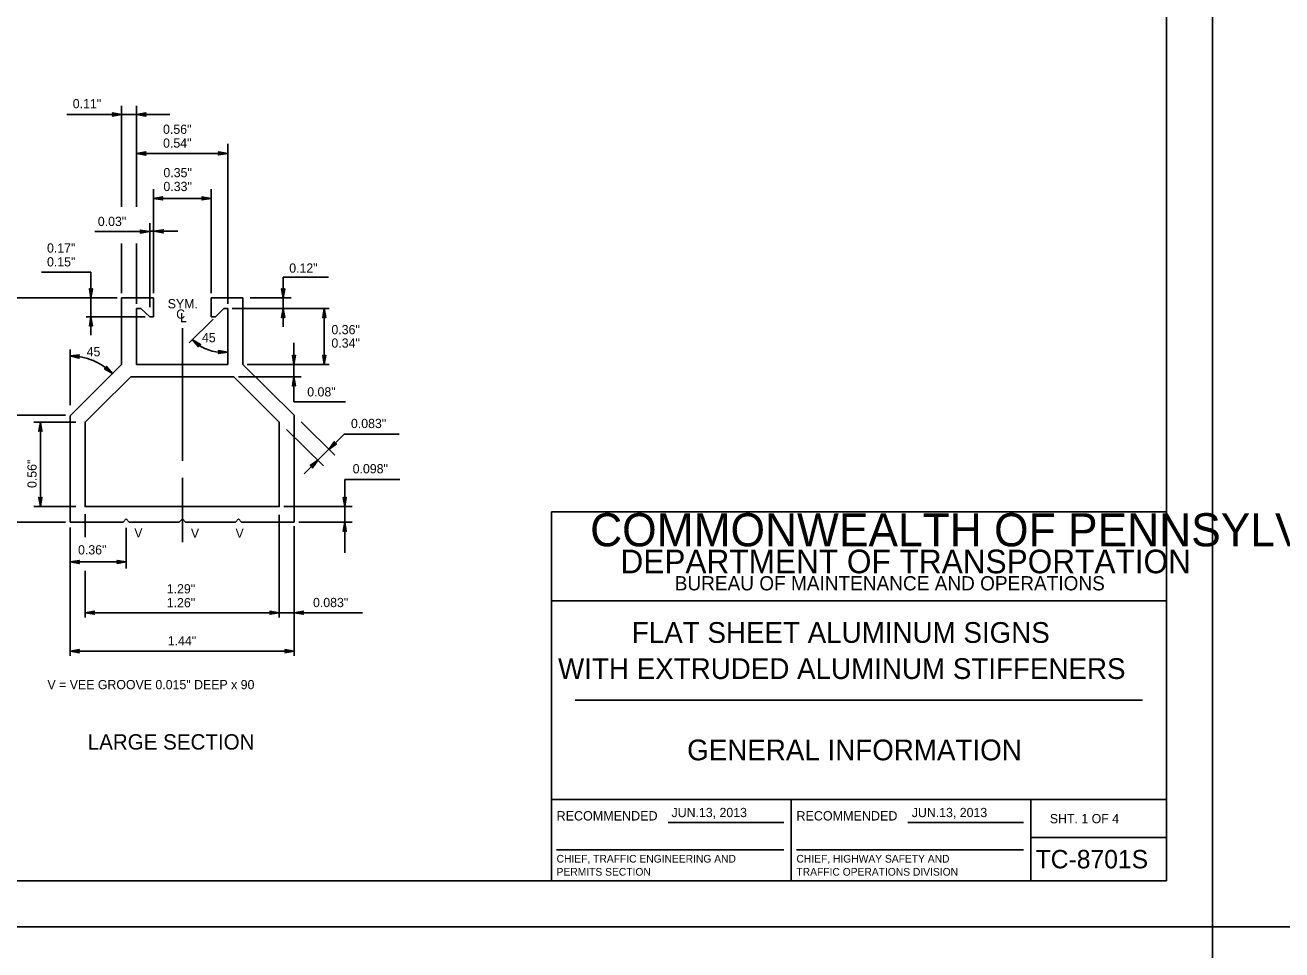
# Model space of a CAD drawing. Extents: x 650495 to 652241, y 298458 to 299646.
# Drawn here: x 650950.2 to 651358.9, y 299044.1 to 299344.9 of the extents above; entities that cross this region are included whole.
import ezdxf

# ---------------------------------------------------------------- set-up
doc = ezdxf.new("R2010")
doc.units = 0
for name, color, linetype in [('1', 7, 'Continuous'), ('2', 7, 'Continuous'), ('3', 7, 'Continuous'), ('PLT-BNDY', 7, 'Continuous')]:
    doc.layers.add(name, color=color, linetype=linetype)

# ---------------------------------------------------------------- blocks, each defined once
blk = doc.blocks.new('RARROW')
at = {"layer": '3'}
blk.add_lwpolyline([(-2.2695, 0.285), (-2.184875, 0.12075), (0, 0), (-2.2695, 0.285), (-2.38575, 0.384625), (0, 0), (-2.183125, -0.108), (-2.262875, -0.2705), (0, 0), (-2.38575, -0.379125), (-2.262875, -0.2705)], dxfattribs=at)

msp = doc.modelspace()

# ---------------------------------------------------------------- linework, layer by layer
at = {"layer": '1'}
for p, q in [((651321.31, 299066.63), (651321.31, 299630.63)), ((651121.31, 299066.63), (651121.31, 299186.63)), ((651121.31, 299186.63), (651321.31, 299186.63)), ((651321.31, 299157.63), (651121.31, 299157.63)), ((651129.06, 299125.31), (651313.56, 299125.31)), ((651121.31, 299093), (651321.31, 299093)), ((651199.31, 299093), (651199.31, 299066.63)), ((651277.19, 299066.63), (651277.19, 299093)), ((651159.24, 299085.57), (651196.87, 299085.57)), ((651237.24, 299085.57), (651274.87, 299085.57)), ((651277.19, 299080.63), (651321.31, 299080.63)), ((651122.99, 299076.68), (651196.87, 299076.68)), ((651200.99, 299076.68), (651274.87, 299076.68)), ((651321.31, 299066.63), (650535.31, 299066.63)), ((650535.31, 299066.63), (651121.31, 299066.63))]:
    msp.add_line(p, q, dxfattribs=at)
at = {"layer": '2'}
for p, q in [((650981.53, 299285.77), (650981.53, 299318.65)), ((650986.41, 299285.77), (650986.41, 299318.65)), ((650963.75, 299315.82), (650981.53, 299315.82)), ((650981.53, 299315.82), (650997.19, 299315.82)), ((651016.03, 299254.27), (651016.03, 299306.22)), ((650986.41, 299303.14), (651016.03, 299303.14)), ((650991.91, 299257.65), (650991.91, 299291.57)), ((651010.66, 299257.65), (651010.66, 299291.57)), ((650991.91, 299288.52), (651010.66, 299288.52)), ((650972.87, 299277.73), (650990.57, 299277.73)), ((650990.66, 299253.19), (650990.66, 299280.52)), ((650990.66, 299277.82), (650999.82, 299277.82)), ((650981.53, 299257.65), (650981.53, 299273.89)), ((650986.41, 299254.27), (650986.41, 299273.89)), ((650955.46, 299264.51), (650971.55, 299264.51)), ((650971.55, 299264.51), (650971.55, 299256.15)), ((651034.07, 299262.9), (651034.07, 299256.15)), ((651034.07, 299262.9), (651048.84, 299262.9)), ((650980.03, 299256.15), (650930.42, 299256.15)), ((650971.55, 299244.02), (650971.55, 299256.15)), ((650981.53, 299234.52), (650981.53, 299256.15)), ((650981.53, 299256.15), (650991.91, 299256.15)), ((650991.91, 299250.02), (650991.91, 299256.15)), ((651010.66, 299256.15), (651020.91, 299256.15)), ((651010.66, 299250.02), (651010.66, 299256.15)), ((651020.91, 299256.15), (651020.91, 299234.52)), ((651023.39, 299256.15), (651036.63, 299256.15)), ((651034.07, 299246.77), (651034.07, 299256.15)), ((650989.16, 299250.02), (650970.05, 299250.02)), ((650986.41, 299252.77), (650986.41, 299234.52)), ((650987.78, 299252.77), (650986.41, 299252.77)), ((650987.78, 299252.77), (650990.66, 299250.02)), ((650990.66, 299250.02), (650991.91, 299250.02)), ((651011.26, 299249.24), (651003.54, 299241.5)), ((651010.66, 299250.02), (651012.04, 299250.02)), ((651014.78, 299252.77), (651012.04, 299250.02)), ((651014.78, 299252.77), (651016.03, 299252.77)), ((651016.03, 299252.77), (651016.03, 299234.52)), ((651017.53, 299252.77), (651048.98, 299252.77)), ((651047.42, 299252.77), (651047.42, 299234.52)), ((651001.28, 299203.15), (651001.28, 299246.34)), ((651037.58, 299241.55), (651037.58, 299234.52)), ((650964.78, 299221.31), (650964.78, 299239.4)), ((651013.4, 299238.53), (651016.03, 299238.53)), ((650964.78, 299217.77), (650981.53, 299234.52)), ((650986.41, 299234.52), (650999.16, 299234.52)), ((651001.28, 299234.52), (651007.78, 299234.52)), ((651007.78, 299234.52), (651016.03, 299234.52)), ((651020.91, 299234.52), (651037.66, 299218.02)), ((651022.41, 299234.52), (651048.98, 299234.52)), ((651037.58, 299234.52), (651037.58, 299222.4)), ((651019.53, 299230.52), (651039.96, 299230.52)), ((651037.58, 299222.4), (651054.37, 299222.4)), ((650963.28, 299218.03), (650937.68, 299218.03)), ((650964.78, 299183.27), (650964.78, 299217.77)), ((651037.66, 299218.02), (651037.66, 299183.27)), ((650952.95, 299215.77), (650966.6, 299215.77)), ((650955.1, 299215.77), (650955.1, 299188.27)), ((651035.2, 299213.38), (651047.2, 299201.57)), ((651039.89, 299215.81), (651050.84, 299205.03)), ((651045.37, 299203.36), (651053.91, 299211.9)), ((651053.91, 299211.9), (651071.77, 299211.9)), ((651040.91, 299198.9), (651045.37, 299203.36)), ((651001.28, 299176.77), (651001.28, 299197.65)), ((651054.09, 299197.15), (651072.05, 299197.15)), ((651054.09, 299197.15), (651054.09, 299188.27)), ((650952.95, 299188.27), (650966.6, 299188.27)), ((651034.28, 299188.27), (651056.47, 299188.27)), ((651054.09, 299188.27), (651054.09, 299173.21)), ((650969.66, 299185.85), (650969.66, 299178.3)), ((650983.03, 299184.27), (650982.03, 299183.27)), ((650984.03, 299183.27), (650983.03, 299184.27)), ((651000.28, 299183.27), (651001.28, 299184.27)), ((651001.28, 299184.27), (651000.28, 299183.27)), ((651002.28, 299183.27), (651001.28, 299184.27)), ((651018.53, 299183.27), (651019.53, 299184.27)), ((651019.53, 299184.27), (651018.53, 299183.27)), ((651019.53, 299184.27), (651020.53, 299183.27)), ((651020.53, 299183.27), (651019.53, 299184.27)), ((651032.78, 299185.62), (651032.78, 299152.27)), ((650963.28, 299183.27), (650930.42, 299183.27)), ((650982.03, 299183.27), (650964.78, 299183.27)), ((650964.78, 299181.46), (650964.78, 299139.77)), ((650983.03, 299181.37), (650983.03, 299168.17)), ((651000.28, 299183.27), (650984.03, 299183.27)), ((651018.53, 299183.27), (651002.28, 299183.27)), ((651037.66, 299183.27), (651020.53, 299183.27)), ((651037.66, 299181.93), (651037.66, 299139.77)), ((651039.16, 299183.27), (651056.47, 299183.27)), ((650964.78, 299170.3), (650983.03, 299170.3)), ((650969.66, 299167.44), (650969.66, 299152.27)), ((650969.66, 299153.77), (651032.78, 299153.77)), ((651059.89, 299153.77), (651032.78, 299153.77)), ((650964.78, 299141.27), (651037.66, 299141.27))]:
    msp.add_line(p, q, dxfattribs=at)
for points in [[(650999.16, 299234.52), (651001.28, 299234.52)], [(650984.53, 299230.52), (650973.78, 299219.9)], [(650999.16, 299230.52), (650984.53, 299230.52)], [(651001.28, 299230.52), (650999.16, 299230.52)], [(651007.78, 299230.52), (651001.28, 299230.52)], [(651018.03, 299230.52), (651007.78, 299230.52)], [(651023.78, 299224.77), (651018.03, 299230.52)], [(651032.78, 299200.15), (651032.78, 299215.77), (651023.78, 299224.77)], [(650973.78, 299219.9), (650969.66, 299215.77), (650969.66, 299188.27), (650973.78, 299188.27)], [(651007.78, 299188.27), (651032.78, 299188.27), (651032.78, 299200.15)], [(650973.78, 299188.27), (651001.28, 299188.27)], [(651001.28, 299188.27), (651005.91, 299188.27)], [(651005.91, 299188.27), (651007.78, 299188.27)]]:
    msp.add_lwpolyline(points, dxfattribs=at)
for centre, radius, start, end in [((651014, 299251.58), 13.06, 223.8098, 267.3752), ((650964.78, 299217.77), 19.5, 45, 90)]:
    msp.add_arc(centre, radius, start, end, dxfattribs=at)
at = {"layer": 'PLT-BNDY'}
for points in [[(650495.31, 299645.63), (651336.31, 299645.63), (651336.31, 299051.63), (650495.31, 299051.63)], [(651336.31, 299645.63), (652177.31, 299645.63), (652177.31, 299051.63), (651336.31, 299051.63)], [(650495.31, 299051.63), (651336.31, 299051.63), (651336.31, 298457.63), (650495.31, 298457.63)], [(651336.31, 299051.63), (652177.31, 299051.63), (652177.31, 298457.63), (651336.31, 298457.63)]]:
    msp.add_lwpolyline(points, close=True, dxfattribs=at)

# ---------------------------------------------------------------- block references
at = {"layer": '2', "xscale": 1.2574347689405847, "yscale": 1.3092961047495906}
for p in [(650981.53, 299315.82), (651016.03, 299303.14), (651010.66, 299288.52), (650990.57, 299277.73), (651016.03, 299238.53), (650983.03, 299170.3), (651032.78, 299153.77), (651037.66, 299141.27)]:
    msp.add_blockref('RARROW', p, dxfattribs=at)
at = {"layer": '2'}
for p, xscale, yscale, rotation in [((650986.41, 299315.82), 1.2574347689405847, 1.3092961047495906, 180), ((650986.41, 299303.14), 1.2574347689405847, 1.3092961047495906, 180), ((650991.91, 299288.52), 1.2574347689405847, 1.3092961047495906, 180), ((650992.09, 299277.82), 1.2574347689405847, 1.3092961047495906, 180), ((650971.55, 299256.15), 1.2574347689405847, 1.3092961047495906, -90.00000000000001), ((651034.07, 299256.15), 1.2574347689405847, 1.3092961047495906, -90.00000000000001), ((650971.55, 299250.02), 1.2574347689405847, 1.3092961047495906, 89.99999999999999), ((651034.07, 299252.77), 1.2574347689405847, 1.3092961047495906, 89.99999999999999), ((651047.42, 299252.77), 1.2574347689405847, 1.3092961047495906, 89.99999999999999), ((651004.57, 299242.54), 1.2574347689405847, 1.3092961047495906, 140.9194989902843), ((650964.78, 299237.27), 1.2574347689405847, 1.3092961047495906, 176.80414646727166), ((651037.58, 299234.52), 1.2574347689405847, 1.3092961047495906, -90.00000000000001), ((651047.42, 299234.52), 1.2574347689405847, 1.3092961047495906, -90.00000000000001), ((650978.57, 299231.56), 1.2574347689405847, 1.3092961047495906, -40.89957129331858), ((651037.58, 299230.52), 1.2574347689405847, 1.3092961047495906, 89.99999999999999), ((650955.1, 299215.77), 1.2574347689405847, 1.3092961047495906, 89.99999999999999), ((651048.93, 299206.89), 1.2574347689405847, 1.3092961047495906, -134.02087905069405), ((651045.37, 299203.36), 1.2574347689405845, 1.3092961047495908, 44.7961575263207), ((650955.1, 299188.27), 1.2574347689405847, 1.3092961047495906, -90.00000000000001), ((651054.09, 299188.27), 1.2574347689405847, 1.3092961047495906, -90.00000000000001), ((651054.09, 299183.27), 1.2574347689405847, 1.3092961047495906, 89.99999999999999), ((650964.78, 299170.3), 1.2574347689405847, 1.3092961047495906, 180), ((650969.66, 299153.77), 1.2574347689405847, 1.3092961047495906, 180), ((651037.66, 299153.77), 1.2574347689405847, 1.3092961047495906, 180), ((650964.78, 299141.27), 1.2574347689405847, 1.3092961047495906, 180)]:
    msp.add_blockref('RARROW', p, dxfattribs=dict(at, xscale=xscale, yscale=yscale, rotation=rotation))

# ---------------------------------------------------------------- texts
at = {"layer": '1'}
for s, height, p in [('COMMONWEALTH OF PENNSYLVANIA', 10.7828, (651133.9, 299175.36)), ('DEPARTMENT OF TRANSPORTATION', 7.6837, (651143.76, 299166.61)), ('BUREAU OF MAINTENANCE AND OPERATIONS', 4.6253, (651161.41, 299161.04)), ('FLAT SHEET ALUMINUM SIGNS', 6.75, (651147.47, 299143.97)), ('WITH EXTRUDED ALUMINUM STIFFENERS', 6.75, (651123.47, 299132.22)), ('GENERAL INFORMATION', 6.75, (651165.45, 299105.78)), ('RECOMMENDED', 3.048, (651122.99, 299086.2)), ('RECOMMENDED', 3.048, (651200.99, 299086.2)), ('SHT. 1 OF 4', 3, (651283.4, 299085.31)), ('CHIEF, TRAFFIC ENGINEERING AND', 2.5, (651122.99, 299072.51)), ('CHIEF, HIGHWAY SAFETY AND', 2.5, (651200.99, 299072.51)), ('TC-8701S', 6, (651278.79, 299070.63)), ('PERMITS SECTION', 2.5, (651122.99, 299068.26)), ('TRAFFIC OPERATIONS DIVISION', 2.5, (651200.99, 299068.26))]:
    msp.add_text(s, height=height, dxfattribs=at).set_placement(p)
at = {"layer": '2'}
for s, height, p in [('0.11"', 3, (650965.65, 299317.84)), ('0.56"', 3, (650995.01, 299309.52)), ('0.54"', 3, (650995.01, 299305.02)), ('0.35"', 3, (650995.13, 299295.41)), ('0.33"', 3, (650995.13, 299290.91)), ('0.03"', 3, (650973.8, 299279.54)), ('0.17"', 3, (650957.26, 299270.9)), ('0.15"', 3, (650957.26, 299266.4)), ('0.12"', 3, (651036.04, 299264.37)), ('SYM.', 3, (650996.53, 299252.77)), ('C', 3, (650999.28, 299249.4)), ('L', 3, (651000.53, 299248.27)), ('45', 3, (651007.65, 299241.75)), ('0.36"', 3, (651049.77, 299244.35)), ('0.34"', 3, (651049.77, 299239.98)), ('45', 3, (650970.16, 299237.15)), ('0.08"', 3, (651041.9, 299224.11)), ('0.083"', 3, (651056.11, 299213.83)), ('0.098"', 3, (651056.67, 299199.11)), ('V', 3, (650985.65, 299178.27)), ('V', 3, (651004.06, 299178.15)), ('V', 3, (651018.57, 299178.15)), ('0.36"', 3, (650967.36, 299172.73)), ('1.29"', 3, (650996.21, 299160.05)), ('1.26"', 3, (650996.21, 299155.55)), ('0.083"', 3, (651043.77, 299155.6)), ('1.44"', 3, (650996.53, 299143.15)), ('V = VEE GROOVE 0.015" DEEP x 90', 3, (650957.41, 299128.9)), ('LARGE SECTION', 5, (650970.5, 299109.26)), ('JUN.13, 2013', 3, (651160.37, 299087.3)), ('JUN.13, 2013', 3, (651238.5, 299087.3))]:
    msp.add_text(s, height=height, dxfattribs=at).set_placement(p)
msp.add_text(' 0.56"', height=3, rotation=90, dxfattribs=at).set_placement((650953.89, 299193.22))

doc.saveas('drawing.dxf')
